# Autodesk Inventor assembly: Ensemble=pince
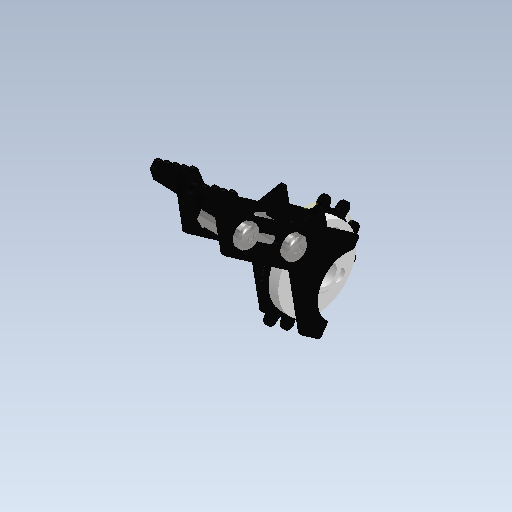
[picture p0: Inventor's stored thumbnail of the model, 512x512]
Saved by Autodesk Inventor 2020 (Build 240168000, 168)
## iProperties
Created: 2021-10
Part Number: Ensemble=pince
Document SubType Name: Assembly
Designer: bruno
Author: bruno
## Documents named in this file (5)
- C:\Users\bruno\OneDrive\Bureau\Robot-Inventor\Pince-Inventor\Ensemble-pince.iam
- C:\Users\bruno\OneDrive\Bureau\Robot-Inventor\Pince-Inventor\Ensemble-doigt.iam
- C:\Users\bruno\OneDrive\Bureau\Robot-Inventor\Pince-Inventor\pince-2.ipt
- C:\Users\bruno\OneDrive\Bureau\Robot-Inventor\Pince-Inventor\embout-servo.ipt
- C:\Users\bruno\Documents\Inventor\Content Center Files\R2020\fr-FR\ANSI B18.6.7M(01)\ANSI B18.6.7M - M3x0,5 x 5(5).ipt
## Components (6 placed, 4 different names)
1. Ensemble-doigt:1 [sub-assembly] — Logement:1, Placage:1, Placage:2, Angle:1, Placage:8
2. pince-2:1 — Logement:1, Placage:3, Placage:4, Placage:5, Placage:6, Angle:1
3. embout-servo:1 — Placage:1, Placage:2, Placage:7
4. Vis à tête tronconique à empreinte cruciforme - Type IA - Métrique M3x0,5 x 5:1 — Placage:3, Placage:4
5. Vis à tête tronconique à empreinte cruciforme - Type IA - Métrique M3x0,5 x 5:2 — Placage:5, Placage:6
6. Vis à tête tronconique à empreinte cruciforme - Type IA - Métrique M3x0,5 x 5:3 — Placage:7, Placage:8
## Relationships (10: Mate 8, Insert 1, Angle 1)
- Logement:1 [Insert]: Ensemble-doigt:1 ↔ pince-2:1
- Placage:1 [Mate]: Ensemble-doigt:1 ↔ embout-servo:1
- Placage:2 [Mate]: Ensemble-doigt:1 ↔ embout-servo:1
- Placage:3 [Mate]: pince-2:1 ↔ Vis à tête tronconique à empreinte cruciforme - Type IA - Métrique M3x0,5 x 5:1
- Placage:4 [Mate]: pince-2:1 ↔ Vis à tête tronconique à empreinte cruciforme - Type IA - Métrique M3x0,5 x 5:1
- Placage:5 [Mate]: pince-2:1 ↔ Vis à tête tronconique à empreinte cruciforme - Type IA - Métrique M3x0,5 x 5:2
- Placage:6 [Mate]: pince-2:1 ↔ Vis à tête tronconique à empreinte cruciforme - Type IA - Métrique M3x0,5 x 5:2
- Angle:1: Ensemble-doigt:1 ↔ pince-2:1
- Placage:7 [Mate]: embout-servo:1 ↔ Vis à tête tronconique à empreinte cruciforme - Type IA - Métrique M3x0,5 x 5:3
- Placage:8 [Mate]: Ensemble-doigt:1 ↔ Vis à tête tronconique à empreinte cruciforme - Type IA - Métrique M3x0,5 x 5:3
